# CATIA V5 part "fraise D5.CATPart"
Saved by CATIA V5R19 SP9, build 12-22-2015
Part number: fraise D5
Bounding box of the stored display mesh (mm): x -3 to 3, y -3 to 3, z 0 to 50
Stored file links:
  Z:\fausse table rondelle-20220905T211342Z-001\fausse table rondelle\fraise D5.CATPart
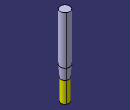
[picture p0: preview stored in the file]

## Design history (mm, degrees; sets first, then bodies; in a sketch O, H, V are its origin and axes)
AxisSystem1: origin (0, 0, 0), X (1, 0, 0), Y (0, 1, 0), Z (0, 0, 1)
Body1 (main body)
  Sketch1 on YZ plane of AxisSystem1, origin (0, 0, 0), H (0, 1, 0), V (0, 0, 1)
    line L1 (0, 0) -> (2.5, 0)
    line L2 (2.5, 0) -> (2.5, 13)
    line L3 (2.5, 13) -> (3, 20)
    line L4 (3, 20) -> (3, 50)
    line L5 (3, 50) -> (0, 50)
    point P5 (0, 50)
    axis line L6 (0, 86.0217) -> (0, -30.1076)
    "Radius" L2 L6 = 2.5
    length L2 = 13
    "Radius" L4 L6 = 3
    distance L5 L1 = 50
    length L4 = 30
    horizontal: L1 H, L5 H
    vertical: L2 V, L4 V, L6 V
    coincidence: P5 V, P5 L6
  Shaft1: profile Sketch1, axis Sketch1.L6, angle 360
